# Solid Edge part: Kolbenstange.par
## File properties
Username: ahadarics
Dokumentum tartalom típus: 0
Author: ahadarics
Last saved by: ahadarics
Revision: 87
Sűrűség: 0,000 kg/m^3
Pontosság: 0,990
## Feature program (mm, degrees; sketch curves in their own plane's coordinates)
base feature "unnamed BaseFeature 1"
sketch for "unnamed Protrusion 1" plane through (63.5, 0, 0) normal (1, 0, 0) x-axis (0, 1, 0)
  circle centre (0, 0) radius 12.5
extrude "unnamed Protrusion 1" add finite 33 along -normal
thread "Menet_1"  ThreadDepth = 22 mm
chamfer "Letörés_1" setback 0.7
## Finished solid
Body 1: solid body, 13 faces, 23 edges, 12 vertices.
  Faces by surface: plane 9, cylinder 3, cone 1
  Edges by curve: line 12, circle 11
Bounding box of the edges (mm): 600.500 x 25.000 x 25.000, from (-537, -12.5, -12.5) to (63.5, 12.5, 12.5).
Cylindrical faces by radius (mm): R5 x2, R12.5 x1
Conical faces (half-angle, radius in mm at the cone's reference point): 45 deg R4.3 x1
Planar faces by outward normal: +x 3, +z 1, -x 4, -z 1
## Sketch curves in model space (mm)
circle centre (63.5, 0, 0) radius 12.5
circle centre (63.5, 0, 0) radius 12.5
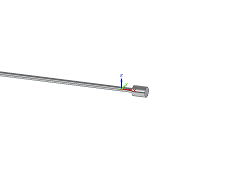
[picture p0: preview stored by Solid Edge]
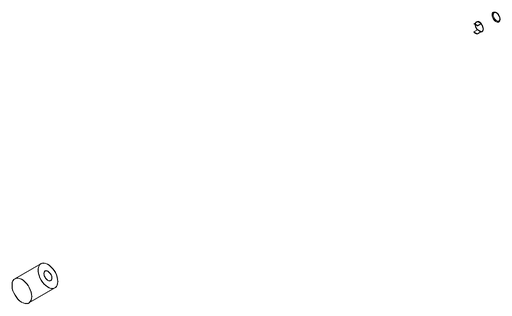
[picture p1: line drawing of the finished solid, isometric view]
